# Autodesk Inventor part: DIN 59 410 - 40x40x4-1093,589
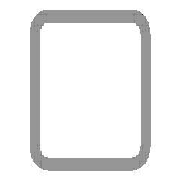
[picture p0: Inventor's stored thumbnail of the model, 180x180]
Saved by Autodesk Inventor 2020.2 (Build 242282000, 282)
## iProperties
Manager: www.cadconsulting.pl
Company: Fabian Stasiak CAD Consulting
IsCustomPart: 1
_CCFamilyMember: 20
_CCFamilyDisplayName: DIN 59410 (Kwadrat) - Rurki stalowe o przekroju kwadratowym formowane na gorąco
_FrameMemberDoc: Frame Member File
_Version: 15.0.0
_GetPNFromCC: 1
Created: 2015-01
Part Number: DIN 59 410 - 40x40x4-1093,589
Material: Stal, miękka
Description: Rurki stalowe o przekroju kwadratowym formowane na gorąco
Document SubType Name: Modellieren
Standard: DIN
Designer: F.Stasiak
Standards Organization: DIN
Language: pl-PL
Size Designation: 40x40x4
Categories: <MemberInstance><Categories><Category DisplayName="Kształtowniki konstrukcyjne" InternalName="089c4875-fa83-4c05-b084-43b9cc11f5ed" Mnemonic="GRDR"><CategoryPar
Stock Number: 40x40x4
Density: 7.85 g/cm^3
Appearance: Częściowo polerowana
Mass: 4423.13 g
Surface Area: 2832.4 cm^2
Volume: 563.456 cm^3
Catalog Web Link: www.expertbooks.pl
G_W: 40,000 mm
G_H: 40,000 mm
+0039B3FF-29B9-484A-9771-7F1A254CC951+CUTDETAIL1: Wytnij
+4B700DF1-F548-4173-9EA5-7F1005C6B704+CUTDETAIL2: Wytnij
G_L: 1093,589 mm
Author: F.Stasiak
Subject: Zbiór ćwiczeń. Autodesk Inventor 2020. Kurs Professional
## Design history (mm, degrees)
node "Płaszczyzna początkowa"
node "Płaszczyzna końcowa"
sketch "Szkic1"
  geometry: L1 (-12, 20)-(12, 20); L2 (20, 12)-(20, -12); L3 (12, -20)-(-12, -20); L4 (-20, -12)-(-20, 12); L5 (-30.32, 0)-(30.32, 0) reference; L6 (0, -30.32)-(0, 30.32) reference; L7 (-12, 16)-(12, 16); L8 (16, 12)-(16, -12); L9 (12, -16)-(-12, -16); L10 (-16, -12)-(-16, 12); A1 r 8 centre (-12, 12) between (-12, 20) and (-20, 12); A2 r 8 centre (12, 12) between (20, 12) and (12, 20); A3 r 8 centre (12, -12) between (12, -20) and (20, -12); A4 r 8 centre (-12, -12) between (-20, -12) and (-12, -20); A5 r 4 centre (-12, 12) between (-12, 16) and (-16, 12); A6 r 4 centre (12, 12) between (16, 12) and (12, 16); A7 r 4 centre (12, -12) between (12, -16) and (16, -12); A8 r 4 centre (-12, -12) between (-16, -12) and (-12, -16); 3 further points
  constraints: 16 end point, 16 point on circle, 8 centre point, 8 tangent, 6 point on line, 4 parallel, 3 equal radius, 3 perpendicular, 1 horizontal, 7 other
  dimensions: "b" = 40 distance of point (-20, 20) point (20, 20); "msp_r" = 8 radius of A1 (= 2 x ParT); "d8" = 20 distance between parallel lines of L4 L6 (= d9); "d9" = 20 distance between parallel lines of L3 L5 (= 0.5 x b); "d10" = 4 distance between parallel lines of L3 L9 (= ParT)
extrude "Bryła" new body sketch "Szkic1" taper "d4" = 0 deg; stored distance "NLG" = 10
node "Driven Length"
  sketch "Sketch2"
    geometry: L1 (0, 0)-(10, 0) reference
    constraints: 2 end point, 1 horizontal
  workplane "Work Plane3"
  sketch "Sketch3"
    geometry: L1 (-2, 15.355)-(12, 15.355) reference; L2 (-2, 1108.944)-(12, 1108.944) reference
    dimensions: "d14" = 1093.5891 distance between parallel lines of L1 L2 (derived)
node "Płaszczyzna konstrukcyjna4"
feature "Podział1"
node "Płaszczyzna konstrukcyjna5"
feature "Podział2"
body "Solid1"
other parameters: "ParT" = 4, "G_OFFSET_START" = -15.35534 [user parameter; used in 1 equation term], "G_OFFSET_END" = -22.42641 [user parameter; used in 1 equation term], "d11" = 15.35534 (= -G_OFFSET_START), "d12" = 1108.94444 (= G_OFFSET_END + B_L), "G_L" = 1093.5891 (= d14) [user parameter], "B_L" = 1131.37085 [user parameter; used in 1 equation term], "d13" = 90 deg
